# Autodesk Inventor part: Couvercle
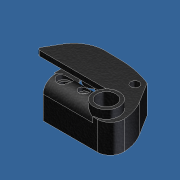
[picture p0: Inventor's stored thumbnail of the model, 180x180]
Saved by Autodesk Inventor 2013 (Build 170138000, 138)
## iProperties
Created: 2011-11
Part Number: Couvercle
Document SubType Name: Modeling
Designer: domi
Density: 1 g/cm^3
Material: Générique
Author: domi
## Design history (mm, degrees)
sketch "Esquisse1"
  geometry: L1 (14.163, -12.705)-(-11.727, -12.705) reference; L2 (11.068, 14.227)-(17.11, 4.559) reference; L3 (-6.841, 15.413)-(-4.84, 17.486) reference; L4 (-9.346, 10.202)-(-7.385, 14.607) reference; L5 (-7.019, 14.445)-(-8.98, 10.04) reference; L6 (-4.673, 17.082)-(-6.553, 15.136) reference; L7 (16.771, 4.347)-(10.798, 13.905) reference; L8 (-11.727, -12.305)-(14.163, -12.305) reference; L9 (-9.346, 10.202)-(-8.98, 10.04); L10 (-11.727, -12.305)-(-11.727, -12.705); A1 r 6.3 centre (14.163, -6.405) between (14.163, -12.705) and (20.455, -6.088) reference; A2 r 22.2 centre (-1.717, -7.205) between (20.455, -6.088) and (17.11, 4.559) reference; A3 r 44.8 centre (-5.727, -27.305) between (11.068, 14.227) and (-4.84, 17.486) reference; A4 r 2.8 centre (-4.827, 13.468) between (-6.841, 15.413) and (-7.385, 14.607) reference; A5 r 2.4 centre (-4.827, 13.468) between (-6.553, 15.136) and (-7.019, 14.445) reference; A6 r 44.4 centre (-5.727, -27.305) between (10.798, 13.905) and (-4.673, 17.082) reference; A7 r 21.8 centre (-1.717, -7.205) between (20.056, -6.109) and (16.771, 4.347) reference; A8 r 5.9 centre (14.163, -6.405) between (14.163, -12.305) and (20.056, -6.109) reference; 1 further point
  constraints: 4 end point, 2 perpendicular
  node "Référence1"
  node "Référence2"
  node "Référence3"
  node "Référence4"
  node "Référence5"
  node "Référence6"
  node "Référence7"
  node "Référence8"
  node "Référence9"
  node "Référence10"
  node "Référence11"
  node "Référence12"
  node "Référence13"
  node "Référence14"
  node "Référence15"
  node "Référence16"
sketch "Esquisse2"
  geometry: C1 r 0.8 at (8.673, 10.845) reference; C2 r 1.77 at (1.773, 8.595) reference; C3 r 2.6 at (12.073, -6.205) reference; C4 r 0.8 at (1.773, -6.605) reference; 1 further point
  node "Référence17"
  node "Référence18"
  node "Référence19"
  node "Référence20"
extrude "Extrusion1" new body sketch "Esquisse1" distance "d0" = 1.9; taper "d1" = 0 deg
sketch "Esquisse4"
  geometry: L1 (-30.234, 18.123)-(20.646, 18.123); L2 (20.646, 18.123)-(20.646, -27.167); L3 (20.646, -27.167)-(-30.234, -27.167); L4 (-30.234, -27.167)-(-30.234, 18.123); 1 further point; 1 other entity
  constraints: 2 other
  dimensions: "d4" = 50.88 distance between parallel lines of L2 L4
  node "Image1"
sketch "Esquisse3"
  geometry: L1 (-11.727, -12.705)-(-11.727, -12.305) reference; L2 (14.163, -12.705)-(-11.727, -12.705) reference; L3 (11.068, 14.227)-(17.11, 4.559) reference; L4 (-6.841, 15.413)-(-4.84, 17.486) reference; L5 (-9.346, 10.202)-(-7.385, 14.607) reference; L6 (-8.98, 10.04)-(-9.346, 10.202) reference; L7 (-7.019, 14.445)-(-8.98, 10.04) reference; L8 (-4.673, 17.082)-(-6.553, 15.136) reference; L9 (16.771, 4.347)-(10.798, 13.905) reference; L10 (-11.727, -12.305)-(14.163, -12.305) reference; L11 (-28.227, 2.095)-(6.773, 2.095); L12 (6.773, 2.095)-(6.773, -1.99); L13 (-11.727, -12.305)-(-11.727, -1.905); L14 (-11.727, -1.905)-(-16.727, -1.905); L15 (-16.727, 2.095)-(-16.727, -1.905); L16 (-4.84, 17.486)-(-12.031, 17.628); L17 (-29.093, 3.595)-(-25.319, 10.131); L18 (-11.727, -1.905)-(6.773, -1.905); A1 r 6.3 centre (14.163, -6.405) between (14.163, -12.705) and (20.455, -6.088) reference; A2 r 22.2 centre (-1.717, -7.205) between (20.455, -6.088) and (17.11, 4.559) reference; A3 r 44.8 centre (-5.727, -27.305) between (11.068, 14.227) and (-4.84, 17.486) reference; A4 r 2.8 centre (-4.827, 13.468) between (-6.841, 15.413) and (-7.385, 14.607) reference; A5 r 2.4 centre (-4.827, 13.468) between (-6.553, 15.136) and (-7.019, 14.445) reference; A6 r 44.4 centre (-5.727, -27.305) between (10.798, 13.905) and (-4.673, 17.082) reference; A7 r 21.8 centre (-1.717, -7.205) between (20.056, -6.109) and (16.771, 4.347) reference; A8 r 5.9 centre (14.163, -6.405) between (14.163, -12.305) and (20.056, -6.109) reference; A9 r 44.8 centre (-5.727, -27.305) between (11.068, 14.227) and (-4.84, 17.486) reference; A10 r 44.8 centre (-5.727, -27.305) between (11.068, 14.227) and (-4.84, 17.486); A11 r 1 centre (-28.227, 3.095) between (-29.093, 3.595) and (-28.227, 2.095); A12 r 15 centre (-12.328, 2.631) between (-12.031, 17.628) and (-25.319, 10.131); 2 further points
  constraints: 16 end point, 7 tangent, 6 point on circle, 4 perpendicular, 3 centre point, 3 point on line, 2 parallel, 1 coincident
  dimensions: "d40" = 10.8 distance between parallel lines of L14 L2; "d41" = 4 distance between parallel lines of L11 L14; "d42" = 1 radius of A11; "d43" = 15 radius of A12; "d44" = 60 deg angle of L11 L17; "d45" = 30 horizontal distance of A11.centre point (1.773, 8.595); "d46" = 5 distance from line of L12 point (1.773, 8.595); "d47" = 23.5 distance between parallel lines of L15 L12
extrude "Extrusion2" join sketch "Esquisse3" distance "d48" = 11.7; taper "d49" = 0 deg
node "Plan de construction1"
sketch "Esquisse7"
  geometry: C1 r 6.1 at (12.073, -6.205); 2 further points
  constraints: 1 centre point, 1 coincident
  dimensions: "d98" = 12.2 diameter of C1
extrude "Extrusion3" join sketch "Esquisse7" stored distance "d100" = 11.7; taper "d101" = 0 deg
node "Plan de construction3"
sketch "Esquisse10"
  geometry: L1 (11.727, -12.305)-(-14.163, -12.305) reference; L2 (11.727, -1.905)-(11.727, -12.305) reference; L3 (-6.773, -1.905)-(11.727, -1.905) reference; L4 (-6.773, 2.095)-(-6.773, -1.905) reference; L5 (28.227, 2.095)-(-6.773, 2.095) reference; L6 (25.319, 10.131)-(29.093, 3.595) reference; L7 (4.84, 17.486)-(12.031, 17.628) reference; L8 (6.841, 15.413)-(4.84, 17.486) reference; L9 (9.346, 10.202)-(7.385, 14.607) reference; L10 (8.98, 10.04)-(9.346, 10.202) reference; L11 (7.019, 14.445)-(8.98, 10.04) reference; L12 (4.673, 17.082)-(6.553, 15.136) reference; L13 (-16.771, 4.347)-(-10.798, 13.905) reference; L14 (-15.923, 3.817)-(-10.124, 13.096); L15 (4.261, 16.07)-(5.834, 14.441); L16 (6.106, 14.038)-(8.067, 9.633); L17 (10.727, -11.277)-(10.727, -11.305); L18 (11.727, -11.305)-(-14.163, -11.305); L19 (9.691, 11.887)-(9.626, 12.032); L20 (8.98, 10.04)-(8.067, 9.633); A1 r 1 centre (28.227, 3.095) between (28.227, 2.095) and (29.093, 3.595) reference; A2 r 15 centre (12.328, 2.631) between (25.319, 10.131) and (12.031, 17.628) reference; A3 r 2.8 centre (4.827, 13.468) between (7.385, 14.607) and (6.841, 15.413) reference; A4 r 2.4 centre (4.827, 13.468) between (7.019, 14.445) and (6.553, 15.136) reference; A5 r 44.4 centre (5.727, -27.305) between (4.673, 17.082) and (-10.798, 13.905) reference; A6 r 21.8 centre (1.717, -7.205) between (-16.771, 4.347) and (-20.056, -6.109) reference; A7 r 5.9 centre (-14.163, -6.405) between (-20.056, -6.109) and (-14.163, -12.305) reference; A8 r 20.8 centre (1.717, -7.205) between (-15.923, 3.817) and (-19.057, -6.159); A9 r 43.4 centre (5.727, -27.305) between (4.261, 16.07) and (-10.124, 13.096); A10 r 1.4 centre (4.827, 13.468) between (6.106, 14.038) and (5.834, 14.441); A11 r 4.9 centre (-14.163, -6.405) between (-19.057, -6.159) and (-14.163, -11.305); 3 further points
  constraints: 14 end point, 9 point on circle, 4 centre point, 3 point on line, 1 perpendicular, 8 other
  dimensions: "d108" = 1 distance between parallel lines of L13 L14
extrude "Extrusion4" cut sketch "Esquisse10" stored distance "d109" = 11.7; taper "d110" = 0 deg
sketch "Esquisse11"
  geometry: L1 (0, -9.2)-(0, 0) reference; L2 (0, 0)-(25.89, 0) reference; L3 (0, 0)-(1.65, 0); L4 (1.65, 0)-(1.65, -7.1); L5 (1.65, -7.1)-(0, -7.1); L6 (0, -7.1)-(0, 0); L7 (0, 1.9)-(25.89, 1.9) reference; 1 further point
  constraints: 8 end point, 2 parallel, 1 horizontal, 1 perpendicular
  dimensions: "d111" = 1.65 distance between parallel lines of L6 L4; "d112" = 9 distance between parallel lines of L5 L7
extrude "Extrusion5" cut sketch "Esquisse11" stored distance "d113" = 11.7; taper "d114" = 0 deg
sketch "Esquisse12"
  geometry: L1 (-2.5, 10.8)-(-2.5, 1.4) reference; L2 (-2.5, 10.8)-(0, 10.8) reference; L3 (-2.5, 10.8)-(-2.5, 5.4); L4 (-2.5, 5.4)-(-2.5, 0); A1 r 5.4 centre (-2.5, 5.4) between (-2.5, 10.8) and (-2.5, 0); 1 further point
  constraints: 4 end point, 2 point on circle, 1 centre point, 1 collinear, 1 perpendicular, 1 point on line
  dimensions: "d115" = 5.4 distance from line of L2 L3.end
sketch "Esquisse13"
  geometry: L1 (-11.727, -12.705)-(-11.727, -1.905) reference; L2 (14.163, -12.705)-(-11.727, -12.705) reference; L3 (11.068, 14.227)-(17.11, 4.559) reference; L4 (-12.031, 17.628)-(-4.84, 17.486) reference; L5 (-29.093, 3.595)-(-25.319, 10.131) reference; L6 (6.773, 2.095)-(-28.227, 2.095) reference; L7 (6.773, -1.905)-(6.773, 2.095) reference; L8 (-11.727, -1.905)-(6.773, -1.905) reference; L9 (6.773, -1.905)-(7.747, -1.905); L10 (12.073, -12.305)-(12.073, -12.705); A1 r 6.1 centre (12.073, -6.205) between (7.747, -1.905) and (12.073, -12.305) reference; A2 r 6.3 centre (14.163, -6.405) between (14.163, -12.705) and (20.455, -6.088) reference; A3 r 22.2 centre (-1.717, -7.205) between (20.455, -6.088) and (17.11, 4.559) reference; A4 r 44.8 centre (-5.727, -27.305) between (11.068, 14.227) and (-4.84, 17.486) reference; A5 r 15 centre (-12.328, 2.631) between (-12.031, 17.628) and (-25.319, 10.131) reference; A6 r 1 centre (-28.227, 3.095) between (-29.093, 3.595) and (-28.227, 2.095) reference; 1 further point
  constraints: 4 end point, 2 point on circle, 1 collinear, 1 perpendicular, 1 point on line
extrude "Extrusion6" cut sketch "Esquisse13" stored distance "d116" = 11.7; taper "d117" = 0 deg
extrude "Extrusion7" join sketch "Esquisse12" stored distance "d118" = 11.7; taper "d119" = 0 deg
sketch "Esquisse15"
  geometry: L1 (0, -2.5)-(0, 0) reference; L2 (0.973, -2.5)-(0, -2.5) reference; L3 (0.973, 0)-(0.973, -2.5) reference; L4 (0, 0)-(0.973, 0) reference; 1 further point
extrude "Extrusion8" join sketch "Esquisse15" stored distance "d120" = 11.7; taper "d121" = 0 deg
sketch "Esquisse16"
  geometry: L1 (0, 0)-(-2.5, 0) reference; L2 (0, 0.4)-(0, 0) reference; L3 (0, 0.4)-(-0.46, 0.4) reference; A1 r 5.4 centre (-2.5, 5.4) between (-2.5, 0) and (-0.46, 0.4) reference; 1 further point
extrude "Extrusion9" cut sketch "Esquisse16" stored distance "d122" = 11.7; taper "d123" = 0 deg
node "Plan de construction4"
sketch "Esquisse17"
  geometry: C1 r 6.1 at (0, 0) reference; 1 further point
extrude "Extrusion10" join sketch "Esquisse17" stored distance "d125" = 11.7; taper "d126" = 0 deg
sketch "Esquisse18"
  geometry: C1 r 6.1 at (0, 0) reference; 1 further point
hole "Perçage1" sketch "Esquisse18" at (0, 0) diameter "d127" = 9; stored, may be unused: countersink angle "d131" = 90 deg, drill point angle "d133" = 118 deg; dims "d128" = 6, "d129" = 4, "d130" = 2, "d132" = 8
node "Plan de construction5"
sketch "Esquisse19"
  geometry: 2 further points
hole "Perçage2" sketch "Esquisse19" at (5, -8.7) diameter "d135" = 2.1; stored, may be unused: countersink angle "d139" = 90 deg, drill point angle "d141" = 118 deg; dims "d136" = 6, "d137" = 4.5, "d138" = 2, "d140" = 8
sketch "Esquisse20"
  geometry: C1 r 1.05 at (5, -8.7) reference; 1 further point
hole "Perçage3" sketch "Esquisse20" at (5, -8.7) diameter "d142" = 4.5; stored, may be unused: countersink angle "d146" = 90 deg, drill point angle "d148" = 0 deg; dims "d143" = 6, "d144" = 4.5, "d145" = 2, "d147" = 2
sketch "Esquisse21"
  geometry: L1 (5, -8.7)-(14.5, -8.7); C1 r 1.05 at (5, -8.7) reference; 2 further points
  constraints: 2 end point, 1 coincident, 1 horizontal
  dimensions: "d149" = 9.5 distance of L1.start L1.end
hole "Perçage4" sketch "Esquisse21" at (14.5, -8.7) diameter "d150" = 4; stored, may be unused: countersink angle "d154" = 90 deg, drill point angle "d156" = 118 deg; dims "d151" = 6, "d152" = 6.1, "d153" = 2.6, "d155" = 2
sketch "Esquisse22"
  geometry: L1 (1.102, 6.362)-(-3.174, 6.362); L2 (-7.39, -13.4)-(18.5, -13.4) reference; L3 (18.5, -4)-(18.5, -13.4) reference; L4 (18.5, -4)-(0, -4) reference; L5 (0, 0)-(0, -4) reference; L6 (35, 0)-(0, 0) reference; L7 (32.092, 8.037)-(35.866, 1.5) reference; L8 (11.613, 15.391)-(18.805, 15.534) reference; L9 (11.613, 15.391)-(13.614, 13.319) reference; L10 (14.158, 12.513)-(16.119, 8.108) reference; L11 (16.119, 8.108)-(14.84, 7.538) reference; L12 (14.84, 7.538)-(12.879, 11.943) reference; L13 (12.607, 12.346)-(11.034, 13.975) reference; L14 (-3.351, 11.002)-(-9.149, 1.722) reference; L15 (2.008, 9.002)-(-1.283, 11.753); L16 (-3.174, 6.362)-(-5.386, 7.745); L17 (-3.174, 6.362)-(-6.25, 6.362); L18 (5, 6.5)-(20.663, 11.425); L19 (16.119, 8.108)-(17.653, 8.791); L20 (15.224, 10.118)-(16.715, 10.781); L21 (14.84, 7.538)-(8.891, 6.23); L22 (8.418, 8.378)-(13.927, 9.59); C1 r 2 at (14.5, -8.7) reference; C2 r 2.25 at (5, -8.7) reference; C3 r 2.05 at (-1.9, 8.75); A1 r 3.9 centre (5, 6.5) between (1.102, 6.362) and (2.008, 9.002); A2 r 1 centre (35, 1) between (35, 0) and (35.866, 1.5) reference; A3 r 15 centre (19.102, 0.537) between (32.092, 8.037) and (18.805, 15.534) reference; A4 r 2.8 centre (11.6, 11.374) between (14.158, 12.513) and (13.614, 13.319) reference; A5 r 1.4 centre (11.6, 11.374) between (12.879, 11.943) and (12.607, 12.346) reference; A6 r 43.4 centre (12.5, -29.4) between (11.034, 13.975) and (-3.351, 11.002) reference; A7 r 20.8 centre (8.49, -9.3) between (-9.149, 1.722) and (-12.284, -8.253) reference; A8 r 4.9 centre (-7.39, -8.5) between (-12.284, -8.253) and (-7.39, -13.4) reference; A9 r 4 centre (20.663, 11.425) between (17.653, 8.791) and (16.715, 10.781); 3 further points
  constraints: 18 end point, 7 point on circle, 4 parallel, 4 point on line, 3 centre point, 2 coincident, 2 horizontal, 2 perpendicular, 1 midpoint, 1 tangent
  dimensions: "d157" = 7.8 diameter of A1; "d158" = 4.1 diameter of C3; "d159" = 2.7 distance from line of L15 point (-1.9, 8.75); "d160" = 2.7 distance from line of L16 point (-1.9, 8.75) (= d159); "d163" = 8 diameter of A9; "d164" = 5.5 distance from line of L18.end L10; "d165" = 2.2 distance between parallel lines of L19 L20; "d166" = 1.1 distance from line of point (5, 6.5) L21 (= 0.5 x d165); "d167" = 2.2 distance between parallel lines of L21 L22 (= d165)
extrude "Extrusion11" join sketch "Esquisse22" stored distance "d161" = 11.7; taper "d162" = 0 deg
sketch "Esquisse23"
  geometry: L1 (-9.947, 8.457)-(-12.16, 9.839) reference; L2 (-12.16, 9.839)-(-15.923, 3.817) reference; L3 (-14.163, -11.305)-(11.727, -11.305) reference; L4 (11.727, -1.905)-(11.727, -11.305) reference; L5 (11.727, -1.905)-(-6.773, -1.905) reference; L6 (-6.773, 2.095)-(-6.773, -1.905) reference; L7 (28.227, 2.095)-(-6.773, 2.095) reference; L8 (25.319, 10.131)-(29.093, 3.595) reference; L9 (10.88, 10.885)-(8.067, 9.633) reference; L10 (8.067, 9.633)-(2.117, 8.324) reference; L11 (-5.671, 8.457)-(-9.947, 8.457) reference; L12 (3.998, 8.738)-(1.237, 3.668); L13 (1.237, 3.668)-(-4.535, 3.524); L14 (-4.535, 3.524)-(-7.545, 8.451); L15 (-7.545, 8.451)-(-4.783, 13.521); L16 (-4.783, 13.521)-(0.988, 13.665); L17 (0.988, 13.665)-(3.998, 8.738); C1 r 2 at (7.727, -6.605) reference; C2 r 2.25 at (-1.773, -6.605) reference; A1 r 20.8 centre (1.717, -7.205) between (-15.923, 3.817) and (-19.057, -6.159) reference; A2 r 4.9 centre (-14.163, -6.405) between (-19.057, -6.159) and (-14.163, -11.305) reference; A3 r 1 centre (28.227, 3.095) between (28.227, 2.095) and (29.093, 3.595) reference; A4 r 15 centre (12.328, 2.631) between (25.319, 10.131) and (14.457, 17.479) reference; A5 r 4 centre (13.889, 13.52) between (10.88, 10.885) and (14.457, 17.479) reference; A6 r 3.9 centre (-1.773, 8.595) between (-5.671, 8.457) and (2.117, 8.324) reference; 3 further points
  constraints: 12 end point, 1 coincident, 1 point on line, 13 other
  dimensions: "d168" = 5 distance from line of L17 point (-1.773, 8.595)
extrude "Extrusion12" cut sketch "Esquisse23" distance "d169" = 5.8; taper "d170" = 0 deg
chamfer "Chanfrein1" distance "d171" = 4.1; stored, may be unused: second distance "d172" = 5.8, angle "d173" = 45 deg
sketch "Esquisse24"
  geometry: L1 (-5.671, 8.457)-(-7.542, 8.457) reference; L2 (3.998, 8.738)-(2.117, 8.324) reference; L3 (3.998, 8.738)-(2.785, 10.724) reference; L4 (1.645, 10.473)-(2.785, 10.724) reference; L5 (-5.685, 11.866)-(-4.765, 11.096) reference; L6 (-5.685, 11.866)-(-7.542, 8.457) reference; A1 r 3.9 centre (-1.773, 8.595) between (-5.671, 8.457) and (2.117, 8.324) reference; A2 r 3.9 centre (-1.773, 8.595) between (1.645, 10.473) and (-4.765, 11.096) reference; 1 further point
hole "Perçage5" sketch "Esquisse24" at (-1.773, 8.595) diameter "d174" = 4.5; stored, may be unused: countersink angle "d178" = 90 deg, drill point angle "d180" = 0 deg; dims "d175" = 6, "d176" = 6.1, "d177" = 2.6, "d179" = 2
sketch "Esquisse25"
  geometry: 2 further points
hole "Perçage6" sketch "Esquisse25" at (-8.673, 10.845) diameter "d181" = 2; stored, may be unused: countersink angle "d185" = 90 deg, drill point angle "d187" = 118 deg; dims "d182" = 6, "d183" = 4.1, "d184" = 2, "d186" = 2
sketch "Esquisse26"
  geometry: L1 (-7.542, 8.457)-(-5.685, 11.866) reference; L2 (-6.32, 10.701)-(-7.276, 8.945); L3 (-7.276, 8.945)-(-9.152, 9.966); L4 (-9.152, 9.966)-(-8.195, 11.723); L5 (-8.195, 11.723)-(-6.32, 10.701); 2 further points
  constraints: 8 end point, 2 parallel, 2 point on line, 1 midpoint, 1 perpendicular
  dimensions: "d188" = 1 distance from line of point (-8.673, 10.845) L3; "d189" = 1 distance from line of L5 point (-8.673, 10.845) (= d188)
extrude "Extrusion13" cut sketch "Esquisse26" stored distance "d190" = 4; taper "d191" = 0 deg
sketch "Esquisse27"
  geometry: L1 (-7.39, -13.4)-(18.5, -13.4) reference; L2 (-7.39, -13.4)-(-0.765, -13.4); C1 r 4.5 at (-5.3, -8.3) reference; A1 r 6.825 centre (-5.3, -8.3) between (-0.765, -13.4) and (-11.477, -11.204); A2 r 4.9 centre (-7.39, -8.5) between (-12.284, -8.253) and (-7.39, -13.4) reference; A3 r 4.9 centre (-7.39, -8.5) between (-11.477, -11.204) and (-7.39, -13.4); 2 further points
  constraints: 6 point on circle, 2 centre point, 2 coincident, 2 end point, 2 tangent, 1 collinear, 1 point on line
extrude "Extrusion14" join sketch "Esquisse27" stored distance "d193" = 4; taper "d194" = 0 deg
sketch "Esquisse28"
  geometry: L1 (-6.816, -1.646)-(-11.218, -2.649); A1 r 20.8 centre (8.49, -9.3) between (-9.149, 1.722) and (-12.284, -8.253) reference; A2 r 6.825 centre (-5.3, -8.3) between (0, -4) and (-11.477, -11.204) reference; A3 r 4.9 centre (-7.39, -8.5) between (-12.284, -8.253) and (-11.477, -11.204) reference; A4 r 20.8 centre (8.49, -9.3) between (-11.218, -2.649) and (-12.284, -8.253); A5 r 6.825 centre (-5.3, -8.3) between (-6.816, -1.646) and (-11.477, -11.204); 1 further point
  constraints: 6 point on circle, 2 centre point, 2 end point, 2 tangent, 1 coincident
extrude "Extrusion15" join sketch "Esquisse28" stored distance "d197" = 10; taper "d198" = 0 deg
fillet "Congé2" dims "d199" = 2.25
sketch "Esquisse29"
  geometry: A1 r 4 centre (0, 0) between (-3.846, -1.1) and (-3.846, 1.1) reference; 1 further point
hole "Perçage7" sketch "Esquisse29" at (0, 0) diameter "d200" = 4.1; stored, may be unused: countersink angle "d204" = 90 deg, drill point angle "d206" = 0 deg; dims "d201" = 6, "d202" = 4, "d203" = 2, "d205" = 8
node "Plan de construction8"
sketch "Esquisse33"
  geometry: C1 r 1 at (0, 0) reference; A1 r 2.05 centre (0, 0) between (1.79, 1) and (1.79, -1) reference; 2 further points
  constraints: 1 coincident, 3 other
extrude "Extrusion16" cut sketch "Esquisse33" stored distance "d210" = 10; taper "d211" = 0 deg
sketch "Esquisse34"
  geometry: L1 (12.924, -4)-(0, -4); L2 (18.5, -4)-(0, -4) reference; L3 (24.663, 11.425)-(24.663, -5); L4 (0.674, -5)-(24.663, -5); A1 r 19.553 centre (-1.9, 8.75) between (12.924, -4) and (17.653, 8.791); A2 r 6.825 centre (-5.3, -8.3) between (-0.765, -13.4) and (-6.816, -1.646) reference; A3 r 4 centre (20.663, 11.425) between (17.653, 8.791) and (16.715, 10.781) reference; A4 r 6.825 centre (-5.3, -8.3) between (0.674, -5) and (0, -4); A5 r 4 centre (20.663, 11.425) between (17.653, 8.791) and (24.663, 11.425); 2 further points
  constraints: 10 point on circle, 6 end point, 3 centre point, 3 coincident, 2 perpendicular, 1 collinear, 1 horizontal, 1 point on line, 1 tangent
  dimensions: "d212" = 1 distance between parallel lines of L4 L1
extrude "Extrusion17" join sketch "Esquisse34" distance "d213" = 0.6; taper "d214" = 0 deg
sketch "Esquisse35"
  geometry: L1 (0, -4)-(12.924, -4) reference; L2 (24.663, -5)-(0.674, -5) reference; L3 (24.663, 11.425)-(24.663, -5) reference; L4 (24.663, 1.925)-(12.924, -4); A1 r 6.825 centre (-5.3, -8.3) between (0.674, -5) and (0, -4) reference; A2 r 4 centre (20.663, 11.425) between (17.653, 8.791) and (24.663, 11.425) reference; A3 r 19.553 centre (-1.9, 8.75) between (12.924, -4) and (17.653, 8.791) reference; 1 further point
  constraints: 2 end point, 1 point on line
  dimensions: "d215" = 9.5 vertical distance of A2.centre L4.start
extrude "Extrusion18" join sketch "Esquisse35" stored distance "d216" = 2.15; taper "d217" = 0 deg
sketch "Esquisse36"
  geometry: L1 (6.625, 0)-(0, 0) reference; L2 (8.064, 8.4)-(32.052, 8.4) reference; L3 (32.052, 8.4)-(32.052, 15.325) reference; L4 (32.052, 15.325)-(20.314, 9.4) reference; L5 (20.314, 9.4)-(7.39, 9.4) reference; L6 (0.574, 11.754)-(-3.828, 10.751) reference; L7 (32.052, 8.4)-(25.89, 8.4); L8 (25.89, 8.4)-(25.89, 10.15); L9 (25.89, 10.15)-(32.052, 10.15); L10 (32.052, 10.15)-(32.052, 8.4); L11 (25.89, 8.4)-(25.89, 0) reference; C1 r 4.5 at (2.09, 5.1) reference; A1 r 4.9 centre (0, 4.9) between (-4.894, 5.147) and (0, 0) reference; A2 r 6.825 centre (2.09, 5.1) between (6.625, 0) and (8.064, 8.4) reference; A3 r 6.825 centre (2.09, 5.1) between (7.39, 9.4) and (0.574, 11.754) reference; A4 r 20.8 centre (15.88, 4.1) between (-3.828, 10.751) and (-4.894, 5.147) reference; 1 further point
  constraints: 8 end point, 2 parallel, 1 collinear, 1 horizontal, 1 perpendicular
  dimensions: "d218" = 1.75 distance between parallel lines of L2 L9
extrude "Extrusion19" cut sketch "Esquisse36" stored distance "d219" = 2.15; taper "d220" = 0 deg
sketch "Esquisse37"
  geometry: L1 (32.052, 15.325)-(20.314, 9.4) reference; L2 (20.179, 8.4)-(32.052, 14.393); L3 (8.064, 8.4)-(25.89, 8.4) reference; L4 (32.052, 10.15)-(32.052, 15.325) reference; L5 (20.179, 8.4)-(32.052, 8.4); L6 (32.052, 8.4)-(32.052, 14.393); 1 further point
  constraints: 6 end point, 2 point on line, 1 parallel
extrude "Extrusion20" cut sketch "Esquisse37" distance "d221" = 0.9; taper "d222" = 0 deg
node "Axe de construction1"
node "Plan de construction6"
sketch "Esquisse38"
  geometry: L1 (57.121, 22.824)-(57.121, 21.76) reference; L2 (57.121, 21.76)-(54.321, 21.76) reference; L3 (54.321, 21.76)-(54.321, 23.8) reference; L4 (54.321, 23.8)-(59.607, 23.8) reference; L5 (59.607, 23.8)-(59.607, 22.824) reference; L6 (59.607, 22.824)-(57.121, 22.824) reference; L7 (57.721, 12.514)-(57.721, 11.271) reference; L8 (57.721, 11.271)-(56.321, 11.271) reference; L9 (56.321, 11.271)-(56.321, 12.514) reference; L10 (56.321, 12.514)-(54.321, 12.514) reference; L11 (54.321, 12.514)-(54.321, 17.84) reference; L12 (54.321, 17.84)-(57.121, 17.84) reference; L13 (57.121, 17.84)-(57.121, 16.776) reference; L14 (57.121, 16.776)-(59.607, 16.776) reference; L15 (59.607, 16.776)-(59.607, 12.514) reference; L16 (59.607, 12.514)-(57.721, 12.514) reference; L17 (57.721, 9.329)-(57.721, 8.086) reference; L18 (57.721, 8.086)-(59.607, 8.086) reference; L19 (59.607, 8.086)-(59.607, 6.1) reference; L20 (59.607, 6.1)-(60.821, 6.1) reference; L21 (60.821, 6.1)-(60.821, 4.5) reference; L22 (60.821, 4.5)-(52.071, 4.5) reference; L23 (52.071, 4.5)-(52.071, 6.825) reference; L24 (52.071, 6.825)-(54.321, 6.825) reference; L25 (54.321, 6.825)-(54.321, 8.086) reference; L26 (54.321, 8.086)-(56.321, 8.086) reference; L27 (56.321, 8.086)-(56.321, 9.329) reference; L28 (56.321, 9.329)-(57.721, 9.329) reference; L29 (56.821, -6.1)-(56.821, -8.387) reference; L30 (56.821, -8.387)-(43.221, -8.387) reference; L31 (43.221, -8.387)-(43.221, -7.986) reference; L32 (43.221, -7.986)-(45.121, -7.986) reference; L33 (45.121, -7.986)-(45.121, -6.986) reference; L34 (45.121, -6.986)-(52.071, -6.986) reference; L35 (52.071, -6.986)-(52.071, -4.5) reference; L36 (52.071, -4.5)-(60.821, -4.5) reference; L37 (60.821, -4.5)-(60.821, -6.1) reference; L38 (60.821, -6.1)-(56.821, -6.1) reference; L39 (56.821, -6.1)-(56.821, -8.387); L40 (56.821, -8.387)-(54.534, -8.387); L41 (54.534, -8.387)-(56.821, -8.387); L42 (56.821, -8.387)-(56.821, -9.387); L43 (56.821, -9.387)-(54.534, -9.387); L44 (54.534, -9.387)-(54.534, -8.387); A1 r 2.287 centre (54.534, -6.1) between (54.534, -8.387) and (56.821, -6.1); 1 further point
  constraints: 12 end point, 3 tangent, 2 parallel, 2 perpendicular, 2 point on circle, 2 point on line, 1 centre point, 1 collinear, 1 horizontal
  dimensions: "d224" = 1 distance between parallel lines of L43 L40
  node "Projeter les arêtes coupées2"
node "Plan de construction7"
sketch "Esquisse39"
  geometry: L1 (56.821, -6.1)-(56.821, -9.816) reference; L2 (56.821, -9.816)-(43.221, -9.816) reference; L3 (43.221, -9.816)-(43.221, -9.377) reference; L4 (43.221, -9.377)-(45.121, -9.377) reference; L5 (45.121, -9.377)-(45.121, -8.273) reference; L6 (45.121, -8.273)-(52.071, -8.273) reference; L7 (52.974, -8.062)-(52.071, -8.062) reference; L8 (52.071, -8.062)-(52.071, -4.5) reference; L9 (52.071, -4.5)-(60.821, -4.5) reference; L10 (60.821, -4.5)-(60.821, -6.1) reference; L11 (60.821, -6.1)-(56.821, -6.1) reference; L12 (58.661, 6.1)-(60.821, 6.1) reference; L13 (60.821, 6.1)-(60.821, 4.5) reference; L14 (60.821, 4.5)-(52.071, 4.5) reference; L15 (52.071, 4.5)-(52.071, 6.825) reference; L16 (52.071, 6.825)-(54.321, 6.825) reference; L17 (54.321, 6.825)-(54.321, 7.212) reference; L18 (54.321, 7.212)-(45.121, 7.212) reference; L19 (45.121, 7.212)-(45.121, 8.627) reference; L20 (45.121, 8.627)-(43.221, 8.627) reference; L21 (43.221, 8.627)-(43.221, 9.192) reference; L22 (43.221, 9.192)-(54.321, 9.192) reference; L23 (56.821, -6.1)-(56.821, -9.816); L24 (56.821, -9.816)-(53.104, -9.816); L25 (53.104, -9.816)-(56.821, -9.816); L26 (56.821, -9.816)-(56.821, -10.816); L27 (56.821, -10.816)-(53.104, -10.816); L28 (53.104, -10.816)-(53.104, -9.816); A1 r 3.716 centre (53.104, -6.1) between (53.104, -9.816) and (56.821, -6.1); 2 further points; 1 other entity
  constraints: 12 end point, 3 point on line, 3 tangent, 2 parallel, 2 perpendicular, 2 point on circle, 1 centre point, 1 collinear, 1 horizontal, 2 other
  dimensions: "d225" = 1 distance between parallel lines of L27 L24
  node "Projeter les arêtes coupées3"
sketch "Esquisse41"
  geometry: L1 (-12.031, 17.628)-(-4.84, 17.486) reference; L2 (11.068, 14.227)-(17.11, 4.559) reference; L3 (14.163, -12.705)-(12.073, -12.705) reference; L4 (12.073, -12.705)-(12.073, -12.305) reference; L5 (10.473, -12.092)-(-11.727, -12.092) reference; L6 (-11.727, -12.092)-(-11.727, -2.519) reference; L7 (-11.727, -2.519)-(6.773, -2.519) reference; L8 (6.773, -2.519)-(6.773, 2.095) reference; L9 (6.773, 2.095)-(-28.227, 2.095) reference; L10 (-29.093, 3.595)-(-25.319, 10.131) reference; L11 (6.773, -2.519)-(7.213, -2.519) reference; C1 r 2.05 at (8.673, 10.845) reference; C2 r 2 at (-7.727, -6.605) reference; C3 r 1.05 at (1.773, -6.605) reference; C4 r 4.5 at (12.073, -6.205) reference; A1 r 44.8 centre (-5.727, -27.305) between (11.068, 14.227) and (-4.84, 17.486) reference; A2 r 22.2 centre (-1.717, -7.205) between (20.455, -6.088) and (17.11, 4.559) reference; A3 r 6.3 centre (14.163, -6.405) between (14.163, -12.705) and (20.455, -6.088) reference; A4 r 6.1 centre (12.073, -6.205) between (10.473, -12.092) and (12.073, -12.305) reference; A5 r 1 centre (-28.227, 3.095) between (-29.093, 3.595) and (-28.227, 2.095) reference; A6 r 15 centre (-12.328, 2.631) between (-12.031, 17.628) and (-25.319, 10.131) reference; A7 r 6.1 centre (12.073, -6.205) between (12.073, -12.305) and (7.213, -2.519) reference; 1 further point
  node "Projeter les arêtes coupées5"
feature "Lissage1" dims "d226" = 0, "d227" = 90 deg, "d228" = 0, "d229" = 90 deg, "d230" = 0, "d231" = 90 deg
  node "Arêtes1"
node "Plan de construction9"
  node "Axe de construction2"
node "Plan de construction10"
  node "Axe de construction3"
node "Plan de construction11"
sketch "Esquisse6"
  geometry: L1 (-29.18, 18.799)-(28.559, 18.799); L2 (28.559, 18.799)-(28.559, -14.001); L3 (28.559, -14.001)-(-29.18, -14.001); L4 (-29.18, -14.001)-(-29.18, 18.799); C1 r 12.123 at (-2.74, 7.872); 1 further point; 1 other entity
  constraints: 1 centre point, 2 other
  dimensions: "d54" = 32.8 distance of L3.end L1.start
  node "Image3"
node "Solide1"
node "Corps solides"
node "Corps surfaciques"
node "Boucle projetée1"
node "Boucle projetée2"
node "Boucle projetée3"
node "Boucle projetée5"
node "Boucle projetée6"
node "Boucle projetée7"
node "Boucle projetée8"
node "Boucle projetée9"
node "Boucle projetée10"
node "Boucle projetée12"
node "Boucle projetée13"
other parameters: "d99" = 17.6, "d106" = -2.5, "d124" = -8.75, "d134" = -5.4 (= -d115), "d207" = 0, "d208" = 45 deg, "d209" = -1.4, "d223" = 90 deg
